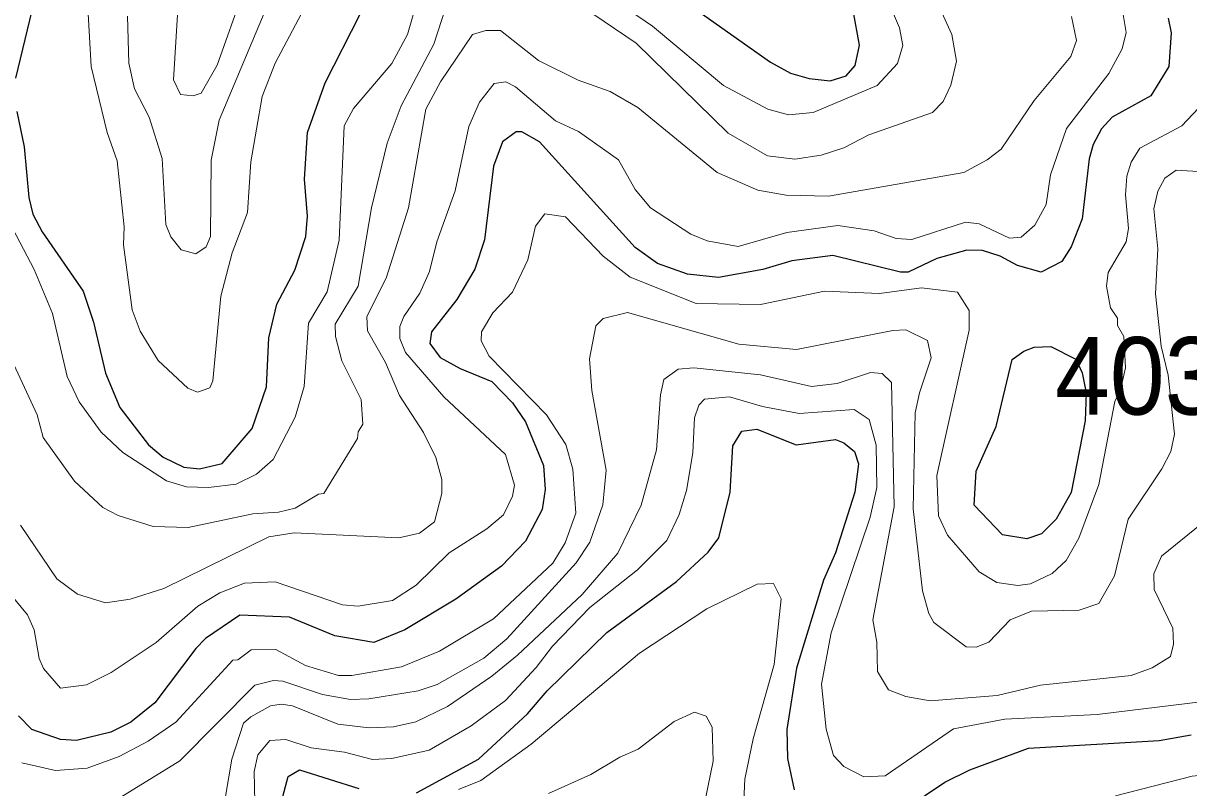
# Model space of a CAD drawing. Extents: x 673.3 to 698.5, y 6984.3 to 7012.3.
# Drawn here: x 681.676 to 682.878, y 6990.189 to 6990.977 of the extents above; entities that cross this region are included whole.
import ezdxf

# ---------------------------------------------------------------- set-up
doc = ezdxf.new("R2010")
doc.units = 0
doc.header["$LTSCALE"] = 0.032
doc.layers.add('1', color=7, linetype='Continuous', lineweight=25)
doc.layers.add('2', color=7, linetype='Continuous', lineweight=13)
doc.layers.add('21', color=7, linetype='Continuous')

msp = doc.modelspace()

# ---------------------------------------------------------------- linework, layer by layer
at = {"layer": '1'}
for points in [[(681.6565, 6991.2103), (681.6951, 6991.1887), (681.7327, 6991.1824), (681.7417, 6991.1687), (681.7424, 6991.1456), (681.7368, 6991.1145), (681.7243, 6991.0797), (681.6846, 6990.9904), (681.6676, 6990.9207)], [(682.3612, 6990.9973), (682.4463, 6990.9373), (682.4671, 6990.9259), (682.4864, 6990.9205), (682.5079, 6990.918), (682.5244, 6990.9231), (682.5337, 6990.934), (682.538, 6990.9549), (682.5315, 6990.9904)], [(682.8564, 6990.9826), (682.8597, 6990.9676), (682.8573, 6990.9328), (682.8385, 6990.9025), (682.7989, 6990.8807), (682.7879, 6990.8687), (682.7793, 6990.8523), (682.7751, 6990.8376), (682.7678, 6990.7757), (682.7566, 6990.7468), (682.7467, 6990.7317), (682.7254, 6990.7209), (682.7011, 6990.7278), (682.6831, 6990.7374), (682.665, 6990.7432), (682.6488, 6990.7436), (682.6179, 6990.7347), (682.5885, 6990.7209), (682.5805, 6990.7209), (682.5108, 6990.7379), (682.4683, 6990.7323), (682.4384, 6990.7236), (682.3928, 6990.7153), (682.3608, 6990.7187), (682.3299, 6990.7297), (682.3069, 6990.7461), (682.2082, 6990.8553), (682.1898, 6990.8656), (682.184, 6990.8654), (682.17, 6990.8551), (682.1605, 6990.8299), (682.1512, 6990.7542), (682.1415, 6990.7238), (682.1229, 6990.6926), (682.0968, 6990.6591), (682.0951, 6990.6471), (682.1057, 6990.6327), (682.1262, 6990.6214), (682.159, 6990.608), (682.1801, 6990.5862), (682.1938, 6990.5666), (682.2123, 6990.5213), (682.214, 6990.4967), (682.2108, 6990.476), (682.1937, 6990.4434), (682.1689, 6990.4178), (682.1217, 6990.3836), (682.0692, 6990.3521), (682.0371, 6990.339), (681.997, 6990.3459), (681.9501, 6990.3649), (681.899, 6990.3671), (681.8637, 6990.343), (681.8535, 6990.3327), (681.8114, 6990.2768), (681.7865, 6990.2568), (681.7659, 6990.2465), (681.7305, 6990.238), (681.7139, 6990.2388), (681.6846, 6990.2494), (681.6708, 6990.2632)], [(681.7752, 6990.5814), (681.8049, 6990.5428), (681.8199, 6990.5299), (681.8412, 6990.5197), (681.8575, 6990.5181), (681.8808, 6990.5234), (681.9118, 6990.5596), (681.9266, 6990.6025), (681.9289, 6990.6529), (681.9372, 6990.6878), (681.9557, 6990.723), (681.9672, 6990.7575), (681.9689, 6990.7785), (681.9657, 6990.8168), (681.9688, 6990.8647), (681.9869, 6990.9159), (682.0232, 6990.9868)], [(681.6691, 6990.8865), (681.6765, 6990.85), (681.6814, 6990.7979), (681.6854, 6990.7806), (681.6952, 6990.7624), (681.7375, 6990.7013), (681.7482, 6990.6692), (681.7606, 6990.6167), (681.7752, 6990.5814)], [(682.0813, 6990.1841), (682.145, 6990.2186), (682.1958, 6990.2654), (682.2161, 6990.289), (682.2777, 6990.3491), (682.3494, 6990.402), (682.3821, 6990.432), (682.3929, 6990.4469), (682.4046, 6990.4939), (682.4076, 6990.5418), (682.4168, 6990.5567), (682.4322, 6990.5588), (682.4729, 6990.5426), (682.5133, 6990.5481), (682.5219, 6990.5449), (682.533, 6990.536), (682.5371, 6990.5232), (682.5332, 6990.4939), (682.5135, 6990.4314), (682.5009, 6990.4031), (682.4732, 6990.3124), (682.4631, 6990.2493), (682.464, 6990.2193), (682.4707, 6990.1872)], [(682.5654, 6990.154), (682.6261, 6990.1948), (682.652, 6990.2078), (682.7126, 6990.2299), (682.8472, 6990.2379), (682.8804, 6990.2437)], [(681.942, 6990.175), (681.9488, 6990.2007), (681.9607, 6990.2078), (682.0217, 6990.1883)]]:
    msp.add_lwpolyline(points, dxfattribs=at)
msp.add_lwpolyline([(682.679, 6990.5618), (682.6955, 6990.6306), (682.7075, 6990.6394), (682.7182, 6990.6433), (682.7355, 6990.6443), (682.7612, 6990.6312), (682.7678, 6990.6171), (682.7718, 6990.5965), (682.7709, 6990.5676), (682.7564, 6990.4935), (682.741, 6990.4662), (682.7259, 6990.451), (682.7107, 6990.4457), (682.6855, 6990.4501), (682.6564, 6990.4804), (682.6585, 6990.5157)], close=True, dxfattribs=at)
at = {"layer": '2'}
for points in [[(681.9026, 6991.011), (681.8755, 6990.9341), (681.8592, 6990.9053), (681.8507, 6990.9025), (681.8379, 6990.9041), (681.8304, 6990.9191), (681.84, 6991.0703)], [(682.1234, 6991.0316), (682.099, 6990.9559), (682.0654, 6990.8922), (682.0509, 6990.8539), (682.0348, 6990.7872), (682.0209, 6990.7065), (681.9974, 6990.667), (681.9977, 6990.6545), (682.0043, 6990.6292), (682.0241, 6990.5896), (682.0258, 6990.5641), (682.021, 6990.5561), (682.0205, 6990.5492), (681.9855, 6990.4925), (681.9803, 6990.4919), (681.9559, 6990.4775), (681.939, 6990.4733), (681.9123, 6990.4716), (681.8456, 6990.4575), (681.8097, 6990.4584), (681.7735, 6990.47), (681.7578, 6990.4782), (681.7283, 6990.5053), (681.696, 6990.5502), (681.6901, 6990.5737), (681.6658, 6990.6256)], [(681.9621, 6990.9869), (681.9354, 6990.9363), (681.9219, 6990.9019), (681.9102, 6990.8347), (681.907, 6990.7822), (681.891, 6990.7407), (681.8793, 6990.6962), (681.8713, 6990.6086), (681.8679, 6990.6015), (681.8552, 6990.5972), (681.8453, 6990.6011), (681.8146, 6990.6298), (681.7961, 6990.66), (681.7881, 6990.6821), (681.7791, 6990.749), (681.7798, 6990.7676), (681.7725, 6990.8354), (681.762, 6990.8647), (681.7455, 6990.9329), (681.7408, 6991.0181)], [(682.0013, 6990.7539), (682.0066, 6990.8715), (682.0163, 6990.8895), (682.0558, 6990.936), (682.0721, 6990.9657), (682.0876, 6991.0207)], [(682.2524, 6991.024), (682.3245, 6990.9743), (682.3978, 6990.9132), (682.4436, 6990.8887), (682.4649, 6990.883), (682.4902, 6990.8854), (682.5563, 6990.9132), (682.5774, 6990.9358), (682.5827, 6990.9544), (682.5794, 6990.9728), (682.564, 6991.0091)], [(681.7831, 6990.9847), (681.7846, 6990.9361), (681.7905, 6990.9098), (681.8054, 6990.8807), (681.8188, 6990.838), (681.8225, 6990.7699), (681.8277, 6990.7572), (681.8384, 6990.7439), (681.8536, 6990.7396), (681.8643, 6990.7468), (681.8686, 6990.7576), (681.8695, 6990.8364), (681.8778, 6990.8776), (681.9339, 6991.0119)], [(682.8081, 6990.9987), (682.8133, 6990.9679), (682.8091, 6990.951), (682.7953, 6990.9255), (682.7518, 6990.869), (682.7352, 6990.8213), (682.7306, 6990.7904), (682.719, 6990.7692), (682.7048, 6990.757), (682.693, 6990.7559), (682.6615, 6990.7707), (682.6476, 6990.7722), (682.5921, 6990.7543), (682.576, 6990.7555), (682.5533, 6990.7634), (682.5157, 6990.769), (682.4631, 6990.7615), (682.413, 6990.7473), (682.3811, 6990.7532), (682.3641, 6990.7598), (682.3227, 6990.7872), (682.3066, 6990.806), (682.2896, 6990.8365), (682.2484, 6990.8657), (682.2245, 6990.8769), (682.1832, 6990.9118)], [(682.6212, 6990.9924), (682.6334, 6990.9657), (682.6383, 6990.9384), (682.6324, 6990.9135), (682.6244, 6990.8968), (682.6135, 6990.8854), (682.5478, 6990.8625), (682.5221, 6990.8489), (682.4987, 6990.8414), (682.4716, 6990.8374), (682.4434, 6990.8406), (682.4028, 6990.8642), (682.3079, 6990.9568), (682.2642, 6990.9865)], [(682.1527, 6990.9701), (682.1677, 6990.9698), (682.2069, 6990.939), (682.2479, 6990.9189), (682.281, 6990.9072), (682.3094, 6990.8906), (682.3913, 6990.8236), (682.4332, 6990.8053), (682.4626, 6990.8002), (682.5062, 6990.7991), (682.6458, 6990.8236), (682.67, 6990.8365), (682.6843, 6990.8477), (682.7183, 6990.8979), (682.7563, 6990.9432), (682.762, 6990.9595), (682.7569, 6990.9845)], [(681.6728, 6990.46), (681.7102, 6990.4045), (681.7316, 6990.3887), (681.7606, 6990.3797), (681.7859, 6990.3837), (681.8205, 6990.3946), (681.929, 6990.448), (681.9549, 6990.4521), (682.063, 6990.4468), (682.0844, 6990.4517), (682.0998, 6990.4634), (682.1073, 6990.4925), (682.1072, 6990.507), (682.1012, 6990.5296), (682.0885, 6990.5555), (682.0637, 6990.5936), (682.0493, 6990.6275), (682.0306, 6990.6602), (682.0299, 6990.6749), (682.05, 6990.7145), (682.0731, 6990.7871), (682.0907, 6990.8888), (682.1058, 6990.9171), (682.139, 6990.9657), (682.1527, 6990.9701)], [(682.1832, 6990.9118), (682.1732, 6990.917), (682.1613, 6990.9154), (682.1461, 6990.8961), (682.1353, 6990.8709), (682.121, 6990.8048), (682.1021, 6990.752), (682.0947, 6990.7215), (682.0846, 6990.6992), (682.068, 6990.6749), (682.0641, 6990.6646), (682.0641, 6990.6525), (682.0699, 6990.6381), (682.1095, 6990.5923), (682.173, 6990.5328), (682.1822, 6990.5013), (682.1803, 6990.4898), (682.171, 6990.4705), (682.1539, 6990.4563), (682.115, 6990.4313), (682.0809, 6990.3982), (682.0563, 6990.3822), (682.0211, 6990.3764), (682.0048, 6990.3778), (681.9354, 6990.4016), (681.9038, 6990.4002), (681.8782, 6990.3901), (681.8556, 6990.3763), (681.8127, 6990.3391), (681.7662, 6990.3081), (681.7407, 6990.2953), (681.714, 6990.2918), (681.6964, 6990.3123), (681.6921, 6990.3225), (681.687, 6990.3519), (681.6799, 6990.3676), (681.662, 6990.3892)], [(682.1608, 6990.3633), (682.2219, 6990.4209), (682.2344, 6990.4418), (682.2456, 6990.4722), (682.2425, 6990.5178), (682.2353, 6990.543), (682.2153, 6990.5737), (682.1562, 6990.6343), (682.1479, 6990.65), (682.1484, 6990.6592), (682.1598, 6990.6787), (682.1803, 6990.7003), (682.1961, 6990.7334), (682.2038, 6990.7681), (682.2135, 6990.781), (682.235, 6990.7777), (682.2736, 6990.7374), (682.3015, 6990.7155), (682.3697, 6990.6884), (682.4359, 6990.6873), (682.5019, 6990.7013), (682.5587, 6990.6989), (682.602, 6990.7045), (682.6392, 6990.7001), (682.6512, 6990.6814), (682.6512, 6990.6611), (682.6178, 6990.5112), (682.6195, 6990.4694), (682.629, 6990.4495), (682.6616, 6990.4117), (682.6797, 6990.4009), (682.7014, 6990.3976), (682.7147, 6990.3993), (682.7368, 6990.4102), (682.7512, 6990.4234), (682.7644, 6990.4466), (682.7851, 6990.5019), (682.8014, 6990.5873), (682.8072, 6990.5994), (682.8124, 6990.622), (682.8109, 6990.6546), (682.8044, 6990.6658), (682.8042, 6990.6733), (682.7972, 6990.684), (682.7929, 6990.7065), (682.7945, 6990.7206), (682.8133, 6990.752), (682.8157, 6990.7657), (682.8125, 6990.8005), (682.8139, 6990.8199), (682.8184, 6990.8343), (682.8272, 6990.8486), (682.8706, 6990.8717), (682.8879, 6990.8897)], [(682.4136, 6990.6465), (682.4732, 6990.6411), (682.5725, 6990.6606), (682.5861, 6990.6613), (682.6082, 6990.6502), (682.6122, 6990.6325), (682.6, 6990.5965), (682.5957, 6990.5757), (682.5935, 6990.4767), (682.6032, 6990.3921), (682.6095, 6990.3688), (682.6148, 6990.3594), (682.6482, 6990.3344), (682.6586, 6990.3341), (682.6717, 6990.3392), (682.6936, 6990.3624), (682.7156, 6990.3714), (682.7647, 6990.3723), (682.7851, 6990.3793), (682.8011, 6990.4076), (682.8151, 6990.4662), (682.85, 6990.5179), (682.8592, 6990.5359), (682.8629, 6990.5539), (682.8565, 6990.6146), (682.8492, 6990.6445), (682.8435, 6990.6983), (682.846, 6990.7449), (682.8419, 6990.7862), (682.8458, 6990.8042), (682.8531, 6990.8176), (682.8649, 6990.8259), (682.9159, 6990.8228)], [(681.6612, 6990.7728), (681.6869, 6990.7236), (681.7056, 6990.678), (681.721, 6990.6132), (681.7334, 6990.5871), (681.756, 6990.5558), (681.7784, 6990.5348), (681.8235, 6990.5056), (681.8439, 6990.4994), (681.8666, 6990.4986), (681.8952, 6990.5023), (681.9161, 6990.5125), (681.9335, 6990.5276), (681.9562, 6990.5712), (681.9655, 6990.6028), (681.9697, 6990.6681), (681.9891, 6990.7006), (682.0013, 6990.7539)], [(681.7761, 6990.1794), (681.8371, 6990.2169), (681.9145, 6990.2949), (681.9336, 6990.2997), (681.9432, 6990.299), (681.9841, 6990.2852), (682.013, 6990.2803), (682.0321, 6990.2809), (682.083, 6990.2891), (682.1026, 6990.2955), (682.1506, 6990.3228), (682.1744, 6990.3427), (682.2458, 6990.4211), (682.2599, 6990.4425), (682.2734, 6990.4809), (682.2767, 6990.5165), (682.262, 6990.5989), (682.2598, 6990.6314), (682.2662, 6990.6654), (682.2737, 6990.6729), (682.2989, 6990.6792), (682.4136, 6990.6465)], [(681.8841, 6990.18), (681.8907, 6990.2187), (681.9029, 6990.2556), (681.9103, 6990.2624), (681.9305, 6990.2737), (681.9417, 6990.2753), (681.9533, 6990.2737), (682, 6990.2548), (682.0325, 6990.251), (682.0576, 6990.2519), (682.0804, 6990.2573), (682.1132, 6990.2731), (682.1588, 6990.3043), (682.1854, 6990.326), (682.2522, 6990.3885), (682.2888, 6990.431), (682.3131, 6990.4804), (682.3287, 6990.5377), (682.3328, 6990.5943), (682.3364, 6990.6101), (682.351, 6990.6206), (682.3673, 6990.6223), (682.436, 6990.6148), (682.4887, 6990.6029), (682.5152, 6990.606), (682.5495, 6990.6174), (682.5616, 6990.6163), (682.5712, 6990.607), (682.5738, 6990.4787), (682.552, 6990.3623), (682.5559, 6990.3392), (682.5567, 6990.3092), (682.5681, 6990.2903), (682.5859, 6990.2834), (682.6111, 6990.2787), (682.68, 6990.2844), (682.7248, 6990.2948), (682.8185, 6990.3048), (682.8399, 6990.3127), (682.859, 6990.3245), (682.8621, 6990.3371)], [(681.9143, 6990.1742), (681.9138, 6990.2059), (681.9175, 6990.2232), (681.9299, 6990.2379), (681.9466, 6990.2388), (681.9726, 6990.2302), (682.0071, 6990.2257), (682.0358, 6990.2184), (682.0559, 6990.2193), (682.0944, 6990.2278), (682.1377, 6990.253), (682.173, 6990.2793), (682.2045, 6990.3131), (682.2214, 6990.3351), (682.2599, 6990.3751), (682.309, 6990.4137), (682.3393, 6990.444), (682.3523, 6990.4708), (682.3598, 6990.4956), (682.3663, 6990.5346), (682.3679, 6990.5705), (682.3726, 6990.5838), (682.3783, 6990.5899), (682.4039, 6990.5922), (682.4381, 6990.5822), (682.476, 6990.5751), (682.5326, 6990.5792), (682.548, 6990.5689), (682.5552, 6990.5423), (682.5559, 6990.4988), (682.5491, 6990.4682), (682.5088, 6990.349), (682.499, 6990.2959), (682.5038, 6990.2496), (682.5114, 6990.2223), (682.522, 6990.211), (682.5425, 6990.2005), (682.5646, 6990.2013), (682.6352, 6990.2498), (682.6882, 6990.26), (682.7832, 6990.2648), (682.9097, 6990.2803)], [(682.8621, 6990.3371), (682.8614, 6990.3538), (682.842, 6990.3935), (682.8419, 6990.4096), (682.8496, 6990.4281), (682.8913, 6990.4616)], [(682.4187, 6990.1757), (682.4198, 6990.198), (682.4285, 6990.2396), (682.4501, 6990.3161), (682.4573, 6990.3839), (682.4494, 6990.3997), (682.4325, 6990.3992), (682.3807, 6990.3735), (682.3113, 6990.3279), (682.1994, 6990.234), (682.1474, 6990.1966), (682.1246, 6990.1875)], [(683.0185, 6990.3899), (683.021, 6990.3794), (683.0405, 6990.3389), (683.0422, 6990.3086), (683.0386, 6990.2863), (683.0256, 6990.2603), (683.0163, 6990.2487), (682.9936, 6990.2303), (682.955, 6990.2143), (682.9211, 6990.2054), (682.8812, 6990.2011), (682.8022, 6990.181)], [(681.6741, 6990.2149), (681.7087, 6990.207), (681.7416, 6990.2095), (681.7744, 6990.2213), (681.8043, 6990.2371), (681.8331, 6990.2569), (681.8919, 6990.3206), (681.897, 6990.3212), (681.9107, 6990.3313), (681.936, 6990.3316), (681.9667, 6990.3151), (682.0006, 6990.3048), (682.0144, 6990.3048), (682.0658, 6990.3137), (682.1051, 6990.3301), (682.1608, 6990.3633)], [(682.2172, 6990.1834), (682.261, 6990.2028), (682.2911, 6990.2207), (682.3098, 6990.2288), (682.347, 6990.2574), (682.3678, 6990.267), (682.38, 6990.2631), (682.3862, 6990.2518), (682.3873, 6990.2165), (682.3759, 6990.1612)]]:
    msp.add_lwpolyline(points, dxfattribs=at)

# ---------------------------------------------------------------- texts
at = {"layer": '21', "width": 0.95}
msp.add_text('403', height=0.08, dxfattribs=at).set_placement((682.7399, 6990.5739))

doc.saveas('drawing.dxf')
